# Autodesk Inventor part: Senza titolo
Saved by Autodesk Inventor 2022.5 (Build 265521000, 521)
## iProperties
Created: 2024-10
Part Number: Senza titolo
Material: Generic
Document SubType Name: Modeling
Designer: AdminForWorker
Density: 1 g/cm^3
Appearance: Default
Title: Senza titolo v2
Author: AdminForWorker
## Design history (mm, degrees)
feature "Body1"
feature "Body2"
body "Solid1"
body "Solid2"
